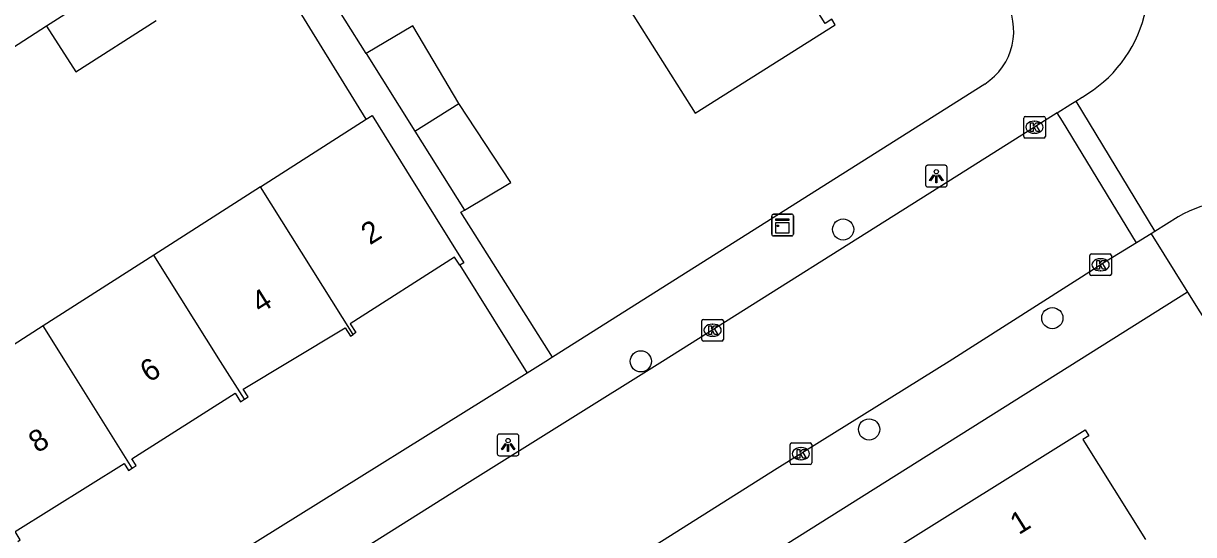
# Model space of a CAD drawing. Extents: x 160077 to 160945, y 386481 to 387498.
# Drawn here: x 160400.2 to 160454.3, y 386992 to 387015.6 of the extents above; entities that cross this region are included whole.
import ezdxf

# ---------------------------------------------------------------- set-up
doc = ezdxf.new("R2010")
doc.units = 0
for name, color, linetype in [('IMGEO_Boom', 7, 'Continuous'), ('IMGEO_Groenvoorziening', 7, 'Continuous'), ('IMGEO_Kast', 7, 'Continuous'), ('IMGEO_Kolk', 7, 'Continuous'), ('IMGEO_Lichtpunt', 7, 'Continuous'), ('IMGEO_Pand', 7, 'Continuous'), ('IMGEO_Pand_nummerreeks', 7, 'Continuous'), ('IMGEO_Rijbaan_lokaal_gesloten', 7, 'Continuous'), ('IMGEO_Rijbaan_lokaal_open', 7, 'Continuous'), ('IMGEO_Voetpad_open', 7, 'Continuous')]:
    doc.layers.add(name, color=color, linetype=linetype)

msp = doc.modelspace()

# ---------------------------------------------------------------- linework, layer by layer
at = {"layer": 'IMGEO_Boom'}
for centre in [(160438.079, 387006.093), (160447.736, 387002.001), (160428.74, 387000.007), (160439.278, 386996.863)]:
    msp.add_circle(centre, 0.489, dxfattribs=at)
at = {"layer": 'IMGEO_Groenvoorziening'}
msp.add_lwpolyline([(160453.975, 387003.205), (160430.516, 386988.451)], dxfattribs=at)
at = {"layer": 'IMGEO_Kast'}
for p, q in [((160434.784, 387005.872), (160434.784, 387006.713)), ((160434.784, 387006.713), (160434.784, 387005.872)), ((160434.859, 387006.797), (160435.7, 387006.797)), ((160435.7, 387006.797), (160434.859, 387006.797)), ((160435.784, 387006.722), (160435.784, 387005.881)), ((160435.784, 387005.881), (160435.784, 387006.722)), ((160435.709, 387005.797), (160434.868, 387005.797)), ((160434.868, 387005.797), (160435.709, 387005.797))]:
    msp.add_line(p, q, dxfattribs=at)
for points in [[(160434.979, 387006.587), (160435.579, 387006.587), (160435.579, 387006.502), (160434.979, 387006.502), (160434.979, 387006.587)], [(160434.979, 387006.412), (160435.579, 387006.412), (160435.579, 387005.923), (160434.979, 387005.923), (160434.979, 387006.412)]]:
    msp.add_lwpolyline(points, dxfattribs=at)
msp.add_circle((160435.063, 387006.261), 0.0377, dxfattribs=at)
for centre, start, end in [((160434.862, 387006.719), 92.4484, 184.2845), ((160434.862, 387006.719), 92.4484, 184.2845), ((160435.706, 387006.719), 2.4484, 94.2845), ((160435.706, 387006.719), 2.4484, 94.2845), ((160434.862, 387005.875), 182.4484, 274.2845), ((160434.862, 387005.875), 182.4484, 274.2845), ((160435.706, 387005.875), 272.4484, 4.2845), ((160435.706, 387005.875), 272.4484, 4.2845)]:
    msp.add_arc(centre, 0.0779, start, end, dxfattribs=at)
at = {"layer": 'IMGEO_Kolk'}
for p, q in [((160446.413, 387010.385), (160446.413, 387011.237)), ((160446.488, 387011.311), (160447.34, 387011.311)), ((160447.414, 387011.237), (160447.414, 387010.385)), ((160446.901, 387011.091), (160446.926, 387011.091)), ((160447.34, 387010.311), (160446.488, 387010.311)), ((160446.924, 387010.531), (160446.899, 387010.531)), ((160449.464, 387004.036), (160449.464, 387004.888)), ((160449.539, 387004.962), (160450.391, 387004.962)), ((160449.952, 387004.742), (160449.977, 387004.742)), ((160450.465, 387004.888), (160450.465, 387004.036)), ((160449.975, 387004.182), (160449.95, 387004.182)), ((160450.391, 387003.962), (160449.539, 387003.962)), ((160431.553, 387001.017), (160431.553, 387001.869)), ((160431.628, 387001.943), (160432.48, 387001.943)), ((160432.041, 387001.723), (160432.066, 387001.723)), ((160432.554, 387001.869), (160432.554, 387001.017)), ((160432.48, 387000.943), (160431.628, 387000.943)), ((160432.064, 387001.163), (160432.039, 387001.163)), ((160435.629, 386995.317), (160435.629, 386996.169)), ((160435.704, 386996.243), (160436.556, 386996.243)), ((160436.63, 386996.169), (160436.63, 386995.317)), ((160436.117, 386996.023), (160436.142, 386996.023)), ((160436.556, 386995.243), (160435.704, 386995.243)), ((160436.14, 386995.463), (160436.115, 386995.463))]:
    msp.add_line(p, q, dxfattribs=at)
for points in [[(160446.413, 387010.385), (160446.413, 387011.237)], [(160446.488, 387011.311), (160447.34, 387011.311)], [(160447.414, 387011.237), (160447.414, 387010.385)], [(160446.734, 387011.011), (160446.857, 387011.011), (160446.857, 387010.86), (160446.987, 387011.011), (160447.151, 387011.011), (160447.005, 387010.86), (160447.158, 387010.611), (160447.006, 387010.611), (160446.921, 387010.775), (160446.857, 387010.708), (160446.857, 387010.611), (160446.734, 387010.611), (160446.734, 387011.011)], [(160447.34, 387010.311), (160446.488, 387010.311)], [(160449.464, 387004.036), (160449.464, 387004.888)], [(160449.539, 387004.962), (160450.391, 387004.962)], [(160450.465, 387004.888), (160450.465, 387004.036)], [(160449.785, 387004.662), (160449.908, 387004.662), (160449.908, 387004.511), (160450.038, 387004.662), (160450.202, 387004.662), (160450.056, 387004.511), (160450.209, 387004.262), (160450.057, 387004.262), (160449.972, 387004.426), (160449.908, 387004.359), (160449.908, 387004.262), (160449.785, 387004.262), (160449.785, 387004.662)], [(160450.391, 387003.962), (160449.539, 387003.962)], [(160431.553, 387001.017), (160431.553, 387001.869)], [(160431.628, 387001.943), (160432.48, 387001.943)], [(160431.874, 387001.643), (160431.997, 387001.643), (160431.997, 387001.492), (160432.127, 387001.643), (160432.291, 387001.643), (160432.145, 387001.492), (160432.298, 387001.243), (160432.146, 387001.243), (160432.061, 387001.407), (160431.997, 387001.34), (160431.997, 387001.243), (160431.874, 387001.243), (160431.874, 387001.643)], [(160432.554, 387001.869), (160432.554, 387001.017)], [(160432.48, 387000.943), (160431.628, 387000.943)], [(160435.629, 386995.317), (160435.629, 386996.169)], [(160435.704, 386996.243), (160436.556, 386996.243)], [(160436.63, 386996.169), (160436.63, 386995.317)], [(160435.95, 386995.943), (160436.073, 386995.943), (160436.073, 386995.792), (160436.203, 386995.943), (160436.367, 386995.943), (160436.221, 386995.792), (160436.374, 386995.543), (160436.222, 386995.543), (160436.137, 386995.707), (160436.073, 386995.64), (160436.073, 386995.543), (160435.95, 386995.543), (160435.95, 386995.943)], [(160436.556, 386995.243), (160435.704, 386995.243)]]:
    msp.add_lwpolyline(points, dxfattribs=at)
for centre, start, end in [((160446.49, 387011.235), 91.552, 178.448), ((160446.49, 387011.235), 91.552, 178.448), ((160447.338, 387011.235), 1.552, 88.448), ((160447.338, 387011.235), 1.552, 88.448), ((160446.49, 387010.387), 181.552, 268.448), ((160446.49, 387010.387), 181.552, 268.448), ((160447.338, 387010.387), 271.552, 358.448), ((160447.338, 387010.387), 271.552, 358.448), ((160449.541, 387004.886), 91.552, 178.448), ((160449.541, 387004.886), 91.552, 178.448), ((160450.389, 387004.886), 1.552, 88.448), ((160450.389, 387004.886), 1.552, 88.448), ((160449.541, 387004.038), 181.552, 268.448), ((160449.541, 387004.038), 181.552, 268.448), ((160450.389, 387004.038), 271.552, 358.448), ((160450.389, 387004.038), 271.552, 358.448), ((160431.63, 387001.867), 91.552, 178.448), ((160431.63, 387001.867), 91.552, 178.448), ((160432.478, 387001.867), 1.552, 88.448), ((160432.478, 387001.867), 1.552, 88.448), ((160431.63, 387001.019), 181.552, 268.448), ((160431.63, 387001.019), 181.552, 268.448), ((160432.478, 387001.019), 271.552, 358.448), ((160432.478, 387001.019), 271.552, 358.448), ((160435.706, 386996.167), 91.552, 178.448), ((160435.706, 386996.167), 91.552, 178.448), ((160436.554, 386996.167), 1.552, 88.448), ((160436.554, 386996.167), 1.552, 88.448), ((160435.706, 386995.319), 181.552, 268.448), ((160435.706, 386995.319), 181.552, 268.448), ((160436.554, 386995.319), 271.552, 358.448), ((160436.554, 386995.319), 271.552, 358.448)]:
    msp.add_arc(centre, 0.0765, start, end, dxfattribs=at)
for centre, major_axis, ratio, start_param, end_param in [((160446.9, 387010.811), (-0.387, 0.002), 0.722429, 4.712389, 7.853982), ((160446.925, 387010.811), (-0.39, 0.002), 0.717154, 1.570796, 4.712389), ((160449.951, 387004.462), (-0.387, 0.002), 0.722429, 4.712389, 7.853982), ((160449.976, 387004.462), (-0.39, 0.002), 0.717154, 1.570796, 4.712389), ((160432.04, 387001.443), (-0.387, 0.002), 0.722429, 4.712389, 7.853982), ((160432.065, 387001.443), (-0.39, 0.002), 0.717154, 1.570796, 4.712389), ((160436.116, 386995.743), (-0.387, 0.002), 0.722429, 4.712389, 7.853982), ((160436.141, 386995.743), (-0.39, 0.002), 0.717154, 1.570796, 4.712389)]:
    msp.add_ellipse(centre, major_axis=major_axis, ratio=ratio, start_param=start_param, end_param=end_param, dxfattribs=at)
at = {"layer": 'IMGEO_Lichtpunt'}
for p, q in [((160442.784, 387009.053), (160441.976, 387009.053)), ((160442.784, 387009.053), (160441.976, 387009.053)), ((160441.882, 387008.958), (160441.882, 387008.151)), ((160441.882, 387008.958), (160441.882, 387008.151)), ((160442.878, 387008.151), (160442.878, 387008.958)), ((160442.878, 387008.151), (160442.878, 387008.958)), ((160441.976, 387008.057), (160442.784, 387008.057)), ((160441.976, 387008.057), (160442.784, 387008.057)), ((160423.018, 386996.646), (160422.21, 386996.646)), ((160423.018, 386996.646), (160422.21, 386996.646)), ((160422.116, 386996.551), (160422.116, 386995.744)), ((160422.116, 386996.551), (160422.116, 386995.744)), ((160423.112, 386995.744), (160423.112, 386996.551)), ((160423.112, 386995.744), (160423.112, 386996.551)), ((160422.21, 386995.65), (160423.018, 386995.65)), ((160422.21, 386995.65), (160423.018, 386995.65))]:
    msp.add_line(p, q, dxfattribs=at)
for points in [[(160442.256, 387008.622), (160442.295, 387008.594), (160442.107, 387008.332), (160442.069, 387008.359), (160442.256, 387008.622)], [(160442.358, 387008.574), (160442.405, 387008.574), (160442.405, 387008.252), (160442.358, 387008.252), (160442.358, 387008.574)], [(160442.468, 387008.594), (160442.506, 387008.621), (160442.693, 387008.359), (160442.654, 387008.331), (160442.468, 387008.594)], [(160422.49, 386996.215), (160422.529, 386996.187), (160422.341, 386995.925), (160422.303, 386995.952), (160422.49, 386996.215)], [(160422.592, 386996.167), (160422.639, 386996.167), (160422.639, 386995.845), (160422.592, 386995.845), (160422.592, 386996.167)], [(160422.702, 386996.187), (160422.74, 386996.214), (160422.927, 386995.952), (160422.888, 386995.924), (160422.702, 386996.187)]]:
    msp.add_lwpolyline(points, dxfattribs=at)
for centre in [(160442.381, 387008.756), (160422.615, 386996.349)]:
    msp.add_circle(centre, 0.0994, dxfattribs=at)
for centre, start, end in [((160441.976, 387008.958), 90, 180), ((160441.976, 387008.958), 90, 180), ((160442.784, 387008.958), 0, 90), ((160442.784, 387008.958), 0, 90), ((160441.976, 387008.151), 180, 270), ((160441.976, 387008.151), 180, 270), ((160442.784, 387008.151), 270, 0), ((160442.784, 387008.151), 270, 360), ((160422.21, 386996.551), 90, 180), ((160422.21, 386996.551), 90, 180), ((160423.018, 386996.551), 0, 90), ((160423.018, 386996.551), 0, 90), ((160422.21, 386995.744), 180, 270), ((160422.21, 386995.744), 180, 270), ((160423.018, 386995.744), 270, 0), ((160423.018, 386995.744), 270, 360)]:
    msp.add_arc(centre, 0.0946, start, end, dxfattribs=at)
at = {"layer": 'IMGEO_Pand'}
for points in [[(160427.937, 387016.702), (160431.243, 387011.463), (160437.712, 387015.544), (160437.555, 387015.794), (160437.253, 387015.604), (160434.202, 387020.439), (160434.473, 387020.61), (160434.375, 387020.765)], [(160405.036, 387017.863), (160401.308, 387015.474)], [(160401.308, 387015.474), (160402.66, 387013.363), (160406.37, 387015.739)], [(160420.343, 387011.909), (160418.21, 387015.488), (160416.061, 387014.208)], [(160416.061, 387014.208), (160418.31, 387010.627)], [(160418.31, 387010.627), (160420.343, 387011.909)], [(160420.595, 387006.988), (160422.745, 387008.268), (160420.343, 387011.909)], [(160411.192, 387008.061), (160416.069, 387011.18)], [(160416.069, 387011.18), (160416.338, 387011.352), (160417.929, 387008.801), (160420.574, 387004.558), (160420.389, 387004.439)], [(160418.31, 387010.627), (160420.595, 387006.988)], [(160411.192, 387008.061), (160406.261, 387004.907)], [(160415.469, 387001.251), (160411.192, 387008.061)], [(160406.261, 387004.907), (160401.15, 387001.638)], [(160410.44, 386998.255), (160409.344, 387000), (160406.261, 387004.907)], [(160420.389, 387004.439), (160420.144, 387004.821), (160415.33, 387001.742), (160415.593, 387001.33), (160415.469, 387001.251)], [(160401.15, 387001.638), (160398.588, 387000), (160395.84, 386998.284)], [(160405.267, 386995.083), (160402.179, 387000), (160401.15, 387001.638)], [(160410.44, 386998.255), (160410.617, 386998.367), (160410.39, 386998.725), (160412.511, 387000), (160415.099, 387001.557), (160415.345, 387001.172), (160415.469, 387001.251)], [(160405.267, 386995.083), (160405.443, 386995.195), (160405.245, 386995.507), (160410.017, 386998.537), (160410.266, 386998.144), (160410.44, 386998.255)], [(160443.983, 386986.571), (160442.966, 386985.934), (160439.826, 386990.947), (160449.256, 386996.847), (160449.426, 386996.576), (160449.148, 386996.402), (160452.03, 386991.789)], [(160399.977, 386991.696), (160400.098, 386991.772), (160399.855, 386992.158), (160404.893, 386995.287), (160405.092, 386994.972), (160405.267, 386995.083)]]:
    msp.add_lwpolyline(points, dxfattribs=at)
at = {"layer": 'IMGEO_Rijbaan_lokaal_gesloten'}
for points in [[(160447.956, 387011.473), (160448.591, 387011.873), (160448.82, 387012.017)], [(160448.82, 387012.017), (160452.472, 387006.002)], [(160451.615, 387005.476), (160448.207, 387011.088), (160447.956, 387011.473)], [(160452.3, 387005.897), (160451.615, 387005.476)], [(160452.472, 387006.002), (160452.3, 387005.897)]]:
    msp.add_lwpolyline(points, dxfattribs=at)
at = {"layer": 'IMGEO_Rijbaan_lokaal_open'}
for points in [[(160448.82, 387012.017), (160449.12, 387012.206)], [(160447.956, 387011.473), (160446.914, 387010.811), (160443.332, 387008.554), (160429.747, 387000), (160420.855, 386994.441), (160404.019, 386983.85), (160393.843, 386977.421), (160392.767, 386976.747)], [(160453.543, 387006.673), (160452.472, 387006.002)], [(160451.615, 387005.476), (160449.965, 387004.462), (160449.803, 387004.359), (160442.967, 387000.002), (160435.029, 386995.058), (160415.556, 386982.761), (160407.317, 386977.588)]]:
    msp.add_lwpolyline(points, dxfattribs=at)
for centre, radius, start, end in [((160446.083, 387017.498), 6.102, 299.8554, 30.4053), ((160456.421, 387001.695), 5.75, 28.7401, 120.0372)]:
    msp.add_arc(centre, radius, start, end, dxfattribs=at)
at = {"layer": 'IMGEO_Voetpad_open'}
for points in [[(160416.069, 387011.18), (160411.314, 387018.906)], [(160416.061, 387014.208), (160414.131, 387017.311)], [(160401.308, 387015.474), (160398.413, 387013.621)], [(160444.618, 387012.806), (160424.667, 387000.196)], [(160424.667, 387000.196), (160420.435, 387006.892), (160420.595, 387006.988)], [(160452.3, 387005.897), (160453.975, 387003.205)], [(160420.389, 387004.439), (160423.489, 386999.46)], [(160453.975, 387003.205), (160473.137, 386972.655)], [(160424.667, 387000.196), (160424.356, 387000), (160423.489, 386999.46)], [(160423.489, 386999.46), (160386.133, 386976.2), (160361.943, 386960.929)]]:
    msp.add_lwpolyline(points, dxfattribs=at)
msp.add_arc((160443.038, 387015.255), 2.915, 302.8254, 31.3564, dxfattribs=at)

# ---------------------------------------------------------------- texts
at = {"layer": 'IMGEO_Pand_nummerreeks'}
for s, rotation, p in [('2', 31.9997, (160416.233, 387005.352)), ('4', 32.0015, (160411.174, 387002.19)), ('6', 32.3021, (160406.037, 386999.003)), ('8', 32.3021, (160400.888, 386995.748)), ('1', 32.0341, (160446.188, 386991.978))]:
    msp.add_text(s, height=1, rotation=rotation, dxfattribs=at).set_placement(p)

doc.saveas('drawing.dxf')
